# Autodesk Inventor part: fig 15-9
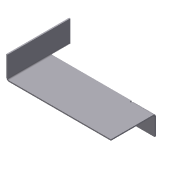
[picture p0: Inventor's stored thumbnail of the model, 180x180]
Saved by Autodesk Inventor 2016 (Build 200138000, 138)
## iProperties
Shininess: 77.0
Angle Display Precision: 2
Document Length Units: 11269
Document Angle Units: 11279
Document Time Units: 11290
Document Mass Units: 11283
Document Length Units Precision: 3
Document Angle Units Precision: 2
Created: 2002-04
Part Number: fig 15-9
Material: Aluminum-6061
Document SubType Name: Sheet Metal
Density: 1 g/cm^3
Sheet Metal Rule: Default
Appearance: Aluminum - Flat-1
Density: 0.0
Volumn: 0.0
Area: 0.0
PropertySet Name: Model Information
Control State: 0
Master: False
Checked Out: False
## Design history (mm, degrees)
node "Face1"
  sketch "Sketch1"
    geometry: L1 (-49.559, 19.574)-(-49.559, -30.426); L2 (-49.559, -30.426)-(50.441, -30.426); L3 (50.441, -30.426)-(50.441, 19.574); L4 (50.441, 19.574)-(32.941, 19.574); L5 (32.941, 19.574)-(32.941, 4.574); L6 (32.941, 4.574)-(-32.059, 4.574); L7 (-32.059, 4.574)-(-32.059, 19.574); L8 (-32.059, 19.574)-(-49.559, 19.574)
    constraints: 16 end point, 6 parallel, 2 equal length, 1 perpendicular, 1 vertical
    dimensions: "d0" = 100 distance of L1.end L2.end; "d1" = 65 distance of L5.end L6.end; "d2" = 15 distance of L6.end L7.end; "d3" = 50 distance of L1.start L1.end
sketch "Sketch2"
  geometry: L1 (100, 0)-(0, 0) reference; L2 (17.5, 50)-(17.5, 35) reference; L3 (82.5, 50)-(82.5, 0)
  constraints: 2 end point, 1 parallel, 1 point on line
sketch "Sketch3"
  geometry: L1 (81.369, -50)-(0, -50) reference; L2 (17.5, 0)-(17.5, -50)
  constraints: 2 end point, 1 perpendicular, 1 point on line
feature "Fold2" sketch "Sketch3" dims "d8" = 1 (= BendRadius), "d9" = 90 deg, "d10" = 1 (= BendRadius), "d14" = 1 (= BendReliefWidth), "d15" = 0.5 (= BendReliefDepth), "d16" = 2 (= MinimumRemnant), "SeamGap" = 0.01, "Thickness" = 1
sketch "Sketch4"
  geometry: L1 (17.5, 0)-(17.5, -50) reference; L2 (-63.869, -15)-(0, -15) reference; L3 (0, -15)-(17.5, -15)
  constraints: 2 end point, 1 collinear, 1 point on line
feature "Fold3" sketch "Sketch4" dims "d11" = 1 (= BendRadius), "d12" = 90 deg, "d13" = 1 (= BendRadius), "d17" = 1 (= BendReliefWidth), "d18" = 0.5 (= BendReliefDepth), "d19" = 2 (= MinimumRemnant), "SeamGap" = 0.01, "Thickness" = 1
body "Solid1"
face "Plate1" dims "Thickness" = 1
other parameters: "BendRadius" = 1 (= Thickness), "BendReliefWidth" = 1 (= Thickness), "BendReliefDepth" = 0.5 (= 0.5 x Thickness), "CornerReliefSize" = 4 (= 4 x Thickness), "MinimumRemnant" = 2 (= 2 x Thickness), "TransitionRadius" = 1 (= BendRadius), "d4" = 1 (= BendRadius), "JacobiRadiusSize" = 1 (= Thickness), "GapSize" = 1 (= Thickness)
